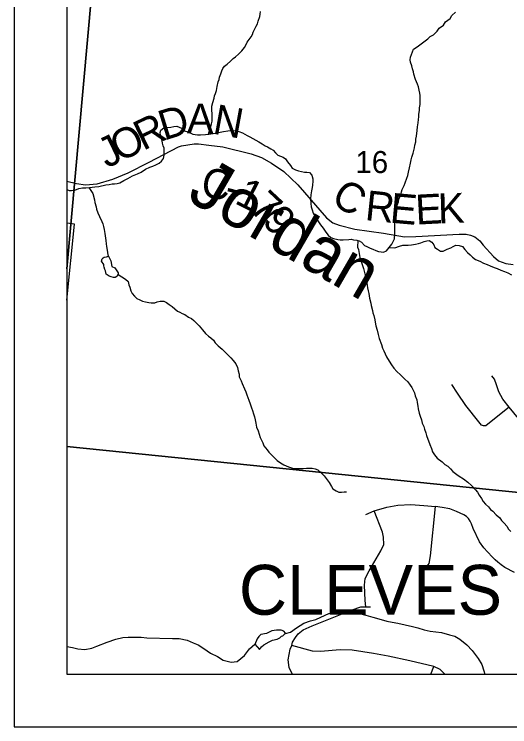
# Model space of a CAD drawing. Extents: x 0 to 34, y 0 to 22.
# Drawn here: x 2 to 2.941, y 14 to 15.353 of the extents above; entities that cross this region are included whole.
import ezdxf

# ---------------------------------------------------------------- set-up
doc = ezdxf.new("R2010")
doc.units = 0
for name, color, linetype in [('Default', 7, 'Continuous'), ('GM_X_Corporation_Text', 7, 'Continuous'), ('GM_X_County_Road', 7, 'Continuous'), ('GM_X_County_Road_Text', 7, 'Continuous'), ('GM_X_Minor_River', 7, 'Continuous'), ('GM_X_Minor_River_Text', 7, 'Continuous'), ('GM_X_Section_Text', 7, 'Continuous'), ('GM_X_State_Route', 7, 'Continuous'), ('GM_X_Township_Road', 7, 'Continuous'), ('SH_Data', 7, 'Continuous')]:
    doc.layers.add(name, color=color, linetype=linetype)

msp = doc.modelspace()

# ---------------------------------------------------------------- linework, layer by layer
at = {"layer": 'Default'}
for points in [[(2.1, 15.5702), (2.1, 14.8697), (2.1629, 15.5646)], [(2.1, 14.8697), (2.1, 14.5322), (3.0761, 14.4328), (3.1681, 15.4277), (2.1629, 15.5646)], [(2.1, 14.9561), (2.1, 14.8103), (2.1145, 14.9545), (2.1098, 14.955)], [(2.1, 14.5322), (2.1, 14.1), (3.0409, 14.1), (3.0761, 14.4328)]]:
    msp.add_lwpolyline(points, close=True, dxfattribs=at)
at = {"layer": 'GM_X_County_Road'}
msp.add_lwpolyline([(2.1, 15.0358), (2.1181, 15.0316), (2.1355, 15.0293), (2.1576, 15.031), (2.187, 15.0397), (2.2166, 15.0518), (2.2562, 15.0724), (2.312, 15.1013), (2.3178, 15.1029), (2.33, 15.105), (2.3421, 15.1068), (2.3502, 15.1072), (2.3698, 15.1044), (2.3963, 15.101), (2.4502, 15.0878), (2.4698, 15.0808), (2.4889, 15.0704), (2.512, 15.0546), (2.539, 15.0292), (2.5935, 14.9667), (2.6054, 14.9572), (2.617, 14.9524), (2.6472, 14.9451), (2.7014, 14.937), (2.7413, 14.9301), (2.7629, 14.9307), (2.8454, 14.9353), (2.8586, 14.9353), (2.8669, 14.9337), (2.8749, 14.9305), (2.8845, 14.9225), (2.8911, 14.9143), (2.9105, 14.8927), (2.9201, 14.8846), (2.9342, 14.8796), (2.9481, 14.8779)], dxfattribs=at)
at = {"layer": 'GM_X_Minor_River'}
for points in [[(2.3688, 15.1252), (2.375, 15.1449), (2.3759, 15.1502), (2.3761, 15.1555), (2.376, 15.1627), (2.3751, 15.1719), (2.3754, 15.1783), (2.3771, 15.1855), (2.3797, 15.1934), (2.3806, 15.1979), (2.3823, 15.2028), (2.384, 15.2084), (2.3854, 15.216), (2.3876, 15.2246), (2.3892, 15.2291), (2.3902, 15.2336), (2.3923, 15.24), (2.3944, 15.2453), (2.3964, 15.2498), (2.3992, 15.2542), (2.4043, 15.2582), (2.4109, 15.2637), (2.4157, 15.2688), (2.4203, 15.2721), (2.4262, 15.2772), (2.4325, 15.2838), (2.4373, 15.2901), (2.4409, 15.2953), (2.4425, 15.2998), (2.4461, 15.305), (2.4501, 15.3098), (2.4525, 15.3147), (2.4542, 15.3192), (2.4571, 15.3251), (2.4595, 15.3304), (2.462, 15.3349), (2.4633, 15.3397), (2.4666, 15.3484), (2.4671, 15.3529), (2.4677, 15.3582)], [(2.7707, 15.2034), (2.769, 15.2087), (2.7677, 15.2149), (2.7659, 15.2202), (2.7624, 15.2291), (2.7594, 15.2391), (2.7584, 15.2437), (2.7563, 15.2491), (2.7554, 15.2552), (2.7529, 15.2617), (2.7523, 15.2663), (2.7525, 15.2716), (2.7563, 15.2817), (2.7583, 15.2866), (2.7653, 15.2909), (2.7758, 15.2989), (2.786, 15.3062), (2.7899, 15.3106), (2.7965, 15.3141), (2.8036, 15.3211), (2.8072, 15.3267), (2.8157, 15.3325), (2.8194, 15.3388), (2.8279, 15.3446), (2.8311, 15.3505), (2.8382, 15.3568)], [(2.4645, 15.1106), (2.4709, 15.107), (2.4768, 15.1034), (2.4813, 15.1009), (2.4876, 15.0973), (2.4921, 15.0949), (2.4965, 15.0898), (2.5009, 15.0854), (2.5058, 15.0838), (2.5106, 15.0817), (2.5154, 15.0785), (2.5194, 15.073), (2.5249, 15.066), (2.5281, 15.061), (2.5341, 15.0577), (2.5401, 15.0556), (2.5457, 15.0543), (2.5514, 15.0533), (2.5559, 15.0528), (2.5612, 15.0522), (2.5656, 15.0471), (2.5673, 15.0406), (2.5675, 15.0357), (2.5665, 15.0285), (2.566, 15.0239), (2.565, 15.0175), (2.5632, 15.0103), (2.5626, 15.0024), (2.5634, 14.9936), (2.564, 14.9875), (2.566, 14.9814), (2.5677, 14.9752), (2.5727, 14.9671), (2.5767, 14.9609), (2.5821, 14.9531), (2.5869, 14.9468), (2.5919, 14.9391), (2.5963, 14.9332), (2.6014, 14.9292), (2.6063, 14.9272), (2.6146, 14.925), (2.6191, 14.9244), (2.6248, 14.9246), (2.6355, 14.9254), (2.64, 14.9256), (2.6445, 14.9243), (2.6506, 14.9241), (2.6551, 14.9228), (2.66, 14.92), (2.6654, 14.9137), (2.6699, 14.9117), (2.6759, 14.9088), (2.6812, 14.9071), (2.6871, 14.9046), (2.692, 14.9025), (2.6969, 14.902), (2.7015, 14.9015), (2.7069, 14.9035), (2.712, 14.9098), (2.7172, 14.9165), (2.72, 14.9213), (2.7221, 14.9266), (2.7228, 14.9357), (2.7233, 14.9501), (2.7231, 14.9569), (2.7226, 14.9634), (2.7227, 14.9683), (2.7238, 14.9782), (2.7263, 14.9846), (2.7273, 14.9906), (2.7298, 14.997), (2.7307, 15.0019), (2.734, 15.0086), (2.737, 15.0199), (2.7407, 15.0281), (2.7428, 15.0326), (2.7458, 15.0416), (2.7478, 15.0465), (2.7488, 15.0533), (2.7506, 15.0616), (2.7528, 15.0703), (2.7538, 15.0763), (2.7555, 15.0819), (2.7576, 15.0891), (2.7603, 15.0993), (2.7608, 15.1042), (2.7626, 15.1106), (2.7631, 15.1159), (2.7641, 15.1212), (2.7656, 15.1321), (2.7662, 15.1393), (2.7676, 15.1469), (2.7678, 15.1529), (2.7687, 15.1582), (2.7689, 15.1635), (2.7699, 15.1703), (2.7701, 15.1753), (2.7711, 15.1813), (2.7714, 15.1919), (2.7709, 15.1984), (2.7707, 15.2034)], [(2.1, 15.0202), (2.1041, 15.0183), (2.1087, 15.0181), (2.1148, 15.0191), (2.1228, 15.0218), (2.1297, 15.0231), (2.1358, 15.0236), (2.1427, 15.0242), (2.1533, 15.0253), (2.1606, 15.0262), (2.1743, 15.0288), (2.1801, 15.0297), (2.1858, 15.031), (2.1904, 15.0312), (2.1957, 15.0314), (2.2003, 15.0328), (2.208, 15.0371), (2.2161, 15.041), (2.2247, 15.046), (2.2343, 15.0499), (2.2412, 15.0534), (2.2494, 15.0585), (2.2575, 15.0624), (2.2633, 15.0648), (2.2687, 15.0669), (2.2752, 15.0705), (2.2799, 15.0737), (2.2835, 15.0789), (2.2845, 15.0854), (2.285, 15.0903), (2.2845, 15.0986), (2.2832, 15.1033), (2.2814, 15.1079), (2.2808, 15.1125), (2.2788, 15.1178), (2.2778, 15.1236), (2.2772, 15.1285), (2.2785, 15.133), (2.284, 15.137), (2.2889, 15.138), (2.2977, 15.1388), (2.3034, 15.1398), (2.3088, 15.1404), (2.3132, 15.1383), (2.3177, 15.1366), (2.3233, 15.1319), (2.3296, 15.1294), (2.3394, 15.1252), (2.3484, 15.1242), (2.3538, 15.124), (2.3633, 15.1244), (2.3694, 15.1253), (2.3781, 15.1266), (2.385, 15.1278), (2.3973, 15.1304), (2.406, 15.1317), (2.4152, 15.1321), (2.4212, 15.1319), (2.4269, 15.1306), (2.4336, 15.1277), (2.4426, 15.1228), (2.4474, 15.1204), (2.453, 15.1171), (2.4589, 15.1139), (2.4645, 15.1106)], [(2.1414, 15.0241), (2.1491, 15.0129), (2.1525, 15.0006), (2.1534, 14.9953), (2.1554, 14.9872), (2.156, 14.9827), (2.1585, 14.9757), (2.162, 14.9688), (2.1663, 14.9595), (2.168, 14.9549), (2.1697, 14.9499), (2.171, 14.9442), (2.1719, 14.9369), (2.1735, 14.9277), (2.1737, 14.9232), (2.1747, 14.9171), (2.1752, 14.9117), (2.1765, 14.9048), (2.1781, 14.8964), (2.1789, 14.8938)], [(2.653, 14.9234), (2.6521, 14.9108), (2.6538, 14.9061), (2.6563, 14.8909), (2.6584, 14.8855), (2.6605, 14.8797), (2.6632, 14.8701), (2.6666, 14.8578), (2.6682, 14.8506), (2.6704, 14.8383), (2.6714, 14.8337), (2.6724, 14.8276), (2.6737, 14.8226), (2.6749, 14.8138), (2.6776, 14.8046), (2.6778, 14.7997), (2.6806, 14.7905), (2.6812, 14.7859), (2.6829, 14.7809), (2.6849, 14.7728), (2.6855, 14.7683), (2.6871, 14.761), (2.6892, 14.7533), (2.6912, 14.7449), (2.6932, 14.7372), (2.6977, 14.726), (2.6998, 14.7191), (2.7022, 14.7137), (2.7047, 14.7083), (2.7075, 14.7025), (2.7122, 14.694), (2.7165, 14.687), (2.7212, 14.6808), (2.7267, 14.6749), (2.7337, 14.6682), (2.7422, 14.6603), (2.748, 14.6548), (2.752, 14.6489), (2.7553, 14.6439), (2.7606, 14.6338), (2.7615, 14.6281), (2.7647, 14.6211), (2.7657, 14.6158), (2.7666, 14.6085), (2.7672, 14.6036), (2.7695, 14.5955), (2.7709, 14.5898), (2.7737, 14.5828), (2.775, 14.5767), (2.7782, 14.5701), (2.7791, 14.5652), (2.7819, 14.5582), (2.7833, 14.5532), (2.7895, 14.5359), (2.7927, 14.5286), (2.7947, 14.522), (2.7983, 14.5162), (2.8034, 14.5103), (2.8127, 14.5028), (2.8178, 14.4981), (2.8238, 14.4948), (2.8289, 14.4897), (2.8329, 14.485), (2.8407, 14.479), (2.8451, 14.4758), (2.8533, 14.4706), (2.8618, 14.4646), (2.8688, 14.4583), (2.8761, 14.4501), (2.8798, 14.4454), (2.8834, 14.4396), (2.8877, 14.4333), (2.8909, 14.4279), (2.8953, 14.4224), (2.9012, 14.4173), (2.9045, 14.4126), (2.9089, 14.4094), (2.9155, 14.4027), (2.9225, 14.3964), (2.9254, 14.3917), (2.9298, 14.387), (2.9364, 14.3803), (2.9385, 14.3757), (2.9437, 14.371)], [(2.712, 14.9098), (2.723, 14.9094), (2.7319, 14.9129), (2.738, 14.9146), (2.7429, 14.9145), (2.7482, 14.9147), (2.7547, 14.9148), (2.762, 14.9165), (2.7677, 14.9178), (2.7727, 14.9191), (2.7788, 14.9216), (2.7838, 14.9229), (2.7884, 14.9231), (2.7932, 14.9199), (2.7968, 14.9149), (2.799, 14.9102), (2.8042, 14.9066), (2.8097, 14.903), (2.815, 14.9032), (2.8224, 14.9068), (2.8293, 14.9092), (2.8339, 14.9117), (2.839, 14.9142), (2.845, 14.9136), (2.8514, 14.9118), (2.8558, 14.9064), (2.8613, 14.9005), (2.8664, 14.8961), (2.8708, 14.8914), (2.8764, 14.8874), (2.8846, 14.8841), (2.8917, 14.8804), (2.8984, 14.8775), (2.9044, 14.875), (2.9119, 14.8721), (2.9172, 14.87), (2.9243, 14.8671), (2.9314, 14.8646), (2.9378, 14.8621), (2.9449, 14.8581)], [(2.1789, 14.8938), (2.1835, 14.885), (2.1851, 14.8739), (2.1908, 14.8715), (2.1952, 14.866), (2.1974, 14.8618), (2.1973, 14.8591), (2.1949, 14.855), (2.1918, 14.8532), (2.1884, 14.8529), (2.1842, 14.8542), (2.1801, 14.8558), (2.1749, 14.8594), (2.1738, 14.8624), (2.1731, 14.8655), (2.1721, 14.8685), (2.171, 14.8724), (2.17, 14.8751), (2.17, 14.8777), (2.166, 14.8839), (2.1673, 14.8885)], [(2.1673, 14.8885), (2.1691, 14.8906), (2.171, 14.8914), (2.1754, 14.8926), (2.1789, 14.8938)], [(2.1972, 14.859), (2.2114, 14.8497), (2.2166, 14.8457), (2.2175, 14.8392), (2.2193, 14.8346), (2.2213, 14.828), (2.2242, 14.8226), (2.2282, 14.8176), (2.233, 14.8132), (2.2386, 14.8104), (2.2438, 14.8083), (2.2491, 14.8066), (2.2559, 14.8056), (2.2604, 14.805), (2.2669, 14.8052), (2.2715, 14.8069), (2.2772, 14.8083), (2.2841, 14.808), (2.2893, 14.8059), (2.2945, 14.802), (2.3, 14.7983), (2.3048, 14.7936), (2.31, 14.7893), (2.3145, 14.7872), (2.3193, 14.7848), (2.3238, 14.7831), (2.3308, 14.7775), (2.3365, 14.7754), (2.3409, 14.7715), (2.3471, 14.7656), (2.3515, 14.7612), (2.3577, 14.7534), (2.3636, 14.7467), (2.3691, 14.7416), (2.3736, 14.7388), (2.3787, 14.7341), (2.3816, 14.729), (2.3875, 14.7235), (2.3948, 14.7168), (2.3992, 14.7125), (2.4058, 14.7065), (2.4117, 14.7006), (2.4161, 14.6955), (2.4208, 14.6889), (2.424, 14.6823), (2.4257, 14.6758), (2.427, 14.6697), (2.4276, 14.6647), (2.4311, 14.6566), (2.4328, 14.652), (2.4374, 14.6416), (2.4399, 14.6358), (2.442, 14.6304), (2.4437, 14.625), (2.4458, 14.62), (2.4482, 14.6135), (2.4506, 14.6058), (2.4527, 14.6004), (2.4544, 14.5939), (2.4565, 14.5885), (2.4574, 14.5831), (2.4587, 14.5763), (2.4603, 14.5686), (2.4631, 14.5617), (2.4673, 14.5494), (2.4722, 14.5393), (2.4743, 14.5332), (2.4805, 14.5261), (2.4838, 14.5214), (2.4885, 14.5163), (2.4937, 14.5112), (2.4995, 14.5057), (2.5055, 14.5013)], [(2.5055, 14.5013), (2.5122, 14.4973), (2.5208, 14.4935), (2.5283, 14.491), (2.5347, 14.4904), (2.5419, 14.4901), (2.5495, 14.4903), (2.5552, 14.4908), (2.5598, 14.491), (2.5662, 14.4912), (2.5719, 14.4899), (2.5768, 14.4878), (2.5823, 14.483), (2.5889, 14.4764), (2.5943, 14.469), (2.5983, 14.4635), (2.603, 14.4565), (2.6055, 14.4518), (2.6118, 14.4478), (2.6167, 14.4454), (2.622, 14.4452), (2.6266, 14.4458), (2.6311, 14.446)], [(2.5154, 14.1772), (2.5248, 14.1796), (2.5364, 14.1877), (2.55, 14.1964), (2.563, 14.201), (2.573, 14.2034), (2.5826, 14.2084), (2.5976, 14.2148), (2.6099, 14.2179), (2.621, 14.2206), (2.6305, 14.2222), (2.6456, 14.2192), (2.6561, 14.215), (2.6678, 14.2117), (2.6814, 14.2079), (2.6968, 14.2036), (2.7077, 14.2006), (2.7179, 14.1985), (2.7285, 14.1966), (2.7428, 14.1936), (2.7568, 14.1901), (2.7666, 14.1876), (2.7786, 14.1838), (2.79, 14.1816), (2.8006, 14.1805), (2.8119, 14.179), (2.827, 14.1748), (2.8368, 14.1719), (2.8465, 14.1666), (2.8599, 14.1556), (2.8698, 14.1451), (2.8811, 14.1295), (2.888, 14.1183), (2.8919, 14.106), (2.8941, 14.1)], [(2.4568, 14.1566), (2.4661, 14.1468), (2.4697, 14.1516), (2.4739, 14.1553), (2.4844, 14.1611), (2.4905, 14.1644), (2.4997, 14.1664), (2.5047, 14.1689), (2.5078, 14.1719), (2.5105, 14.1729), (2.5156, 14.1774), (2.5122, 14.1813), (2.507, 14.1837), (2.4979, 14.1832), (2.4891, 14.1819)], [(2.4891, 14.1819), (2.4795, 14.1772), (2.4684, 14.1752), (2.4645, 14.1715), (2.4617, 14.167), (2.4569, 14.1565)], [(2.1, 14.1521), (2.1104, 14.1504), (2.1209, 14.1482), (2.1338, 14.1467), (2.1472, 14.1494), (2.1572, 14.1533), (2.1764, 14.1607), (2.1929, 14.1663), (2.2066, 14.1694), (2.2165, 14.1698), (2.2313, 14.1698), (2.2412, 14.1699), (2.2518, 14.1688), (2.3008, 14.1674), (2.3133, 14.1678), (2.3288, 14.1647), (2.3397, 14.1595), (2.3494, 14.1554), (2.3599, 14.1486), (2.3729, 14.1399), (2.386, 14.1334), (2.3972, 14.1267), (2.4123, 14.1228), (2.4233, 14.1236), (2.4377, 14.135), (2.4468, 14.148), (2.4568, 14.1566)]]:
    msp.add_lwpolyline(points, dxfattribs=at)
at = {"layer": 'GM_X_State_Route'}
msp.add_lwpolyline([(2.1, 16.7408), (2.1, 14.1), (5.0661, 14.1), (5.1035, 14.4713), (5.1456, 14.8898), (5.1715, 15.1469), (5.2499, 15.926)], dxfattribs=at)
at = {"layer": 'GM_X_Township_Road'}
msp.add_line((2.7916, 14.1), (2.7971, 14.1145), dxfattribs=at)
for points in [[(2.9578, 14.5856), (2.9403, 14.6069), (2.928, 14.6223), (2.9243, 14.6289), (2.9206, 14.6361), (2.9164, 14.6493), (2.9124, 14.66), (2.9073, 14.6666)], [(2.9403, 14.6069), (2.9029, 14.5773), (2.8959, 14.5717), (2.8939, 14.5711), (2.8912, 14.5713), (2.8878, 14.5727), (2.8826, 14.5789), (2.8579, 14.6103), (2.8423, 14.6334), (2.8316, 14.65)], [(2.6678, 14.2278), (2.6668, 14.2398), (2.6655, 14.2687), (2.6665, 14.2815), (2.6741, 14.296), (2.6964, 14.3338), (2.702, 14.346), (2.7017, 14.3598), (2.6994, 14.3697), (2.6839, 14.4098)], [(2.6678, 14.4029), (2.6839, 14.4098), (2.7076, 14.417), (2.7286, 14.421), (2.7533, 14.4223), (2.778, 14.4203), (2.8, 14.418)], [(2.777, 14.2947), (2.7882, 14.3101), (2.7908, 14.3246), (2.8, 14.418)], [(2.9504, 14.2928), (2.9319, 14.3024), (2.9253, 14.3074), (2.9189, 14.3123), (2.9134, 14.3168), (2.9086, 14.3223), (2.8988, 14.3324), (2.892, 14.3397), (2.8841, 14.3512), (2.8719, 14.3764), (2.8685, 14.3856), (2.8664, 14.3901), (2.8628, 14.3957), (2.859, 14.3994), (2.8542, 14.4027), (2.8403, 14.4087), (2.8277, 14.4141), (2.813, 14.4165), (2.8, 14.418)], [(2.5283, 14.1), (2.5281, 14.1003), (2.5223, 14.1122), (2.5204, 14.1271), (2.5244, 14.1473), (2.5274, 14.1543), (2.5285, 14.1605), (2.534, 14.1692), (2.5394, 14.1766), (2.5487, 14.184), (2.5662, 14.1917), (2.6421, 14.2219), (2.6586, 14.2278)], [(2.6586, 14.2278), (2.6678, 14.2278), (2.6769, 14.2277)], [(2.8182, 14.1), (2.8091, 14.109), (2.7971, 14.1145), (2.7518, 14.1249), (2.7101, 14.1341), (2.6825, 14.1389), (2.6422, 14.1454), (2.619, 14.1458), (2.5815, 14.1431), (2.5665, 14.1436), (2.5274, 14.1543)]]:
    msp.add_lwpolyline(points, dxfattribs=at)
at = {"layer": 'SH_Data'}
for p, q in [((2, 21), (2, 14)), ((2.1, 20.9), (2.1, 14.1)), ((2.1, 14.1), (8.9, 14.1)), ((2.1, 14.1), (2.1, 14.1)), ((2, 14), (9, 14))]:
    msp.add_line(p, q, dxfattribs=at)

# ---------------------------------------------------------------- texts
at = {"layer": 'GM_X_Corporation_Text'}
msp.add_text('CLEVES', height=0.0947, rotation=0, dxfattribs=at).set_placement((2.4269, 14.2127))
at = {"layer": 'GM_X_County_Road_Text'}
for s, rotation, p in [('A', 359.2933, (2.3278, 15.1269)), ('N', 349.5827, (2.3753, 15.1266)), ('D', 17.1425, (2.2846, 15.1129)), ('R', 25.873, (2.2448, 15.0933)), ('O', 25.9565, (2.1998, 15.0715)), ('J', 25.9526, (2.1759, 15.0598)), ('C', 349.4612, (2.3522, 15.0078)), ('1', 333.2825, (2.4167, 14.9949)), ('C', 328.437, (2.5992, 14.9956)), ('-', 345.6918, (2.3971, 14.9995)), ('7', 316.7988, (2.4444, 14.9816)), ('R', 354.0693, (2.665, 14.9623)), ('E', 354.9106, (2.7124, 14.9574)), ('E', 3.0273, (2.7635, 14.9534)), ('K', 1.7743, (2.8056, 14.9557)), ('9', 311.9085, (2.4691, 14.9586))]:
    msp.add_text(s, height=0.0568, rotation=rotation, dxfattribs=at).set_placement(p)
at = {"layer": 'GM_X_Minor_River_Text'}
msp.add_text('Jordan', height=0.0947, rotation=329.9306, dxfattribs=at).set_placement((2.3252, 15.0019))
at = {"layer": 'GM_X_Section_Text'}
msp.add_text('16', height=0.04186, rotation=0, dxfattribs=at).set_placement((2.6481, 15.0514))

doc.saveas('drawing.dxf')
